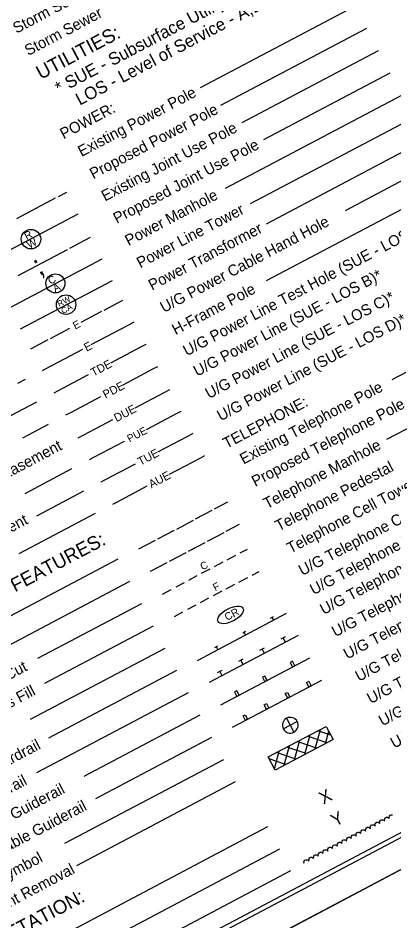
# Model space of a CAD drawing. Extents: x 1487118 to 1489121, y 496367 to 498126.
# Drawn here: x 1488120 to 1488418, y 496745 to 497462 of the extents above; entities that cross this region are included whole.
import ezdxf

# ---------------------------------------------------------------- set-up
doc = ezdxf.new("R2010")
doc.units = 0
for name, color, linetype in [('Prop Easement Permanent Drainage Utility', 7, 'Continuous'), ('Prop WCC CELL', 7, 'Continuous'), ('Sheet Cutting Line CELL', 7, 'Continuous'), ('Sheet Plot Border Inside CELL', 7, 'Continuous'), ('Sheet Plot Border Outside CELL', 7, 'Continuous'), ('Sheet Symbology CELL', 7, 'Continuous')]:
    doc.layers.add(name, color=color, linetype=linetype)

msp = doc.modelspace()

# ---------------------------------------------------------------- linework, layer by layer
at = {"layer": 'Prop Easement Permanent Drainage Utility'}
for p, q in [((1488212.57, 497152.15), (1488240.16, 497166.72)), ((1488167.2, 497128.2), (1488194.88, 497142.81))]:
    msp.add_line(p, q, dxfattribs=at)
at = {"layer": 'Prop WCC CELL'}
msp.add_ellipse((1488288.33, 496987.68), major_axis=(9.92, 5.24), ratio=0.462467, dxfattribs=at)
at = {"layer": 'Sheet Cutting Line CELL'}
msp.add_line((1487631.63, 496367.31), (1489120.78, 497153.62), dxfattribs=at)
at = {"layer": 'Sheet Plot Border Inside CELL'}
msp.add_lwpolyline([(1487632.64, 496393.24), (1489106.32, 497171.37), (1488613.66, 498104.39), (1487139.99, 497326.26)], close=True, dxfattribs=at)
at = {"layer": 'Sheet Plot Border Outside CELL'}
msp.add_lwpolyline([(1487631.63, 496367.31), (1489120.78, 497153.62), (1488607.16, 498126.35), (1487118.01, 497340.04)], close=True, dxfattribs=at)
at = {"layer": 'Sheet Symbology CELL'}
for p, q in [((1488386.91, 497470.85), (1488264.26, 497406.09)), ((1488396.25, 497453.16), (1488280.49, 497392.04)), ((1488405.59, 497435.48), (1488297.25, 497378.27)), ((1488414.93, 497417.79), (1488314.55, 497364.79)), ((1488424.27, 497400.11), (1488284.11, 497326.1)), ((1488433.61, 497382.42), (1488304.06, 497314.02)), ((1488442.95, 497364.73), (1488316.58, 497298.01)), ((1488452.28, 497347.05), (1488379.48, 497308.61)), ((1488151.63, 497319.88), (1488158.27, 497323.38)), ((1488461.62, 497329.36), (1488316.69, 497252.83)), ((1488118.47, 497302.37), (1488149.42, 497318.71)), ((1488094.44, 497267.57), (1488167.39, 497306.1)), ((1488160.73, 497278.83), (1488177.2, 497287.53)), ((1488119.69, 497257.16), (1488158.96, 497277.9)), ((1488113.32, 497231.82), (1488186.28, 497270.34)), ((1488121.51, 497214.76), (1488194.46, 497253.28)), ((1488187.99, 497229.68), (1488202.79, 497237.49)), ((1488169.64, 497219.99), (1488186.22, 497228.74)), ((1488515.56, 497226.63), (1488416.62, 497174.39)), ((1488177.7, 497202.25), (1488207.55, 497218.01)), ((1488207.55, 497218.01), (1488211.87, 497220.29)), ((1488145.32, 497207.15), (1488160.79, 497215.32)), ((1488129.83, 497198.97), (1488143.55, 497206.21)), ((1488217.54, 497200.67), (1488221.21, 497202.6)), ((1488141.23, 497182.99), (1488171.07, 497198.75)), ((1488193.22, 497187.83), (1488217.54, 497200.67)), ((1488534.24, 497191.26), (1488412.32, 497126.89)), ((1488138.92, 497181.77), (1488141.23, 497182.99)), ((1488202.96, 497170.35), (1488227.28, 497183.19)), ((1488227.28, 497183.19), (1488230.55, 497184.92)), ((1488125.08, 497174.46), (1488119.18, 497171.35)), ((1488151.22, 497165.65), (1488175.54, 497178.49)), ((1488148.25, 497164.08), (1488151.22, 497165.65)), ((1488160.95, 497148.17), (1488185.27, 497161.01)), ((1488134.08, 497156.6), (1488113.61, 497145.79)), ((1488157.59, 497146.4), (1488160.95, 497148.17)), ((1488221.67, 497134.99), (1488245.99, 497147.83)), ((1488245.99, 497147.83), (1488249.23, 497149.54)), ((1488143.42, 497138.91), (1488122.95, 497128.1)), ((1488230.58, 497117.07), (1488254.9, 497129.91)), ((1488254.9, 497129.91), (1488258.57, 497131.85)), ((1488179.67, 497112.81), (1488203.99, 497125.65)), ((1488176.27, 497111.02), (1488179.67, 497112.81)), ((1488239.92, 497099.39), (1488264.24, 497112.23)), ((1488264.24, 497112.23), (1488267.91, 497114.17)), ((1488162.1, 497103.53), (1488124.84, 497083.86)), ((1488188.58, 497094.89), (1488212.89, 497107.74)), ((1488185.61, 497093.33), (1488188.58, 497094.89)), ((1488197.91, 497077.21), (1488222.23, 497090.05)), ((1488171.44, 497085.85), (1488134.18, 497066.17)), ((1488194.95, 497075.64), (1488197.91, 497077.21)), ((1488275.64, 497071.77), (1488286.25, 497077.37)), ((1488180.78, 497068.16), (1488120.24, 497036.2)), ((1488260.6, 497063.83), (1488273.87, 497070.83)), ((1488245.57, 497055.89), (1488258.83, 497062.9)), ((1488284.97, 497054.08), (1488295.59, 497059.69)), ((1488230.54, 497047.96), (1488243.8, 497054.96)), ((1488269.94, 497046.14), (1488283.21, 497053.15)), ((1488215.5, 497040.02), (1488228.77, 497047.02)), ((1488254.91, 497038.21), (1488268.17, 497045.21)), ((1488239.87, 497030.27), (1488253.14, 497037.27)), ((1488301.48, 497039.64), (1488295.82, 497036.65)), ((1488198.85, 497031.87), (1488108.34, 496984.08)), ((1488292.37, 497034.83), (1488285.43, 497031.17)), ((1488224.84, 497022.33), (1488238.11, 497029.34)), ((1488272.03, 497024.09), (1488265.13, 497020.45)), ((1488282.15, 497029.44), (1488275.3, 497025.82)), ((1488261.64, 497018.61), (1488254.92, 497015.06)), ((1488301.71, 497017.15), (1488294.76, 497013.48)), ((1488310.81, 497021.96), (1488305.15, 497018.97)), ((1488208.19, 497014.19), (1488060.38, 496936.14)), ((1488251.47, 497013.24), (1488244.79, 497009.71)), ((1488291.49, 497011.75), (1488284.64, 497008.13)), ((1488234.4, 497004.23), (1488241.12, 497007.77)), ((1488270.98, 497000.92), (1488264.26, 496997.37)), ((1488281.37, 497006.41), (1488274.47, 497002.77)), ((1488217.53, 496996.5), (1488135.12, 496952.99)), ((1488260.81, 496995.55), (1488254.13, 496992.03)), ((1488243.74, 496986.54), (1488250.46, 496990.09)), ((1488262, 496951.62), (1488332.75, 496988.97)), ((1488320.2, 496985.18), (1488322.41, 496986.35)), ((1488322.48, 496983.55), (1488321.31, 496985.76)), ((1488226.86, 496978.82), (1488140.44, 496933.18)), ((1488298.1, 496973.51), (1488300.31, 496974.67)), ((1488300.37, 496971.88), (1488299.2, 496974.09)), ((1488342.08, 496971.29), (1488271.34, 496933.93)), ((1488328.5, 496968.58), (1488332.04, 496970.45)), ((1488332.11, 496966.02), (1488330.27, 496969.52)), ((1488236.2, 496961.13), (1488129.27, 496904.67)), ((1488275.99, 496961.83), (1488278.2, 496963)), ((1488278.26, 496960.21), (1488277.09, 496962.42)), ((1488311.7, 496959.71), (1488315.24, 496961.58)), ((1488315.31, 496957.15), (1488313.47, 496960.65)), ((1488280.68, 496916.25), (1488351.42, 496953.6)), ((1488294.9, 496950.84), (1488298.43, 496952.71)), ((1488298.51, 496948.28), (1488296.67, 496951.77)), ((1488245.35, 496943.48), (1488143.8, 496889.86)), ((1488278.1, 496941.97), (1488281.63, 496943.84)), ((1488281.71, 496939.41), (1488279.86, 496942.9)), ((1488290.02, 496898.56), (1488360.76, 496935.92)), ((1488254.69, 496925.79), (1488134.21, 496862.18)), ((1488264.02, 496908.11), (1488171.79, 496859.4)), ((1488332.9, 496905.64), (1488335.82, 496900.12)), ((1488335.82, 496900.12), (1488341.34, 496903.03)), ((1488318.29, 496874.89), (1488364.36, 496899.22)), ((1488330.29, 496897.2), (1488335.82, 496900.12)), ((1488335.82, 496900.12), (1488338.73, 496894.59)), ((1488355.59, 496881.35), (1488359.81, 496896.81)), ((1488368.08, 496892.19), (1488357.78, 496895.74)), ((1488363.77, 496885.67), (1488366.42, 496895.33)), ((1488364.36, 496899.22), (1488369.83, 496888.87)), ((1488273.36, 496890.42), (1488181.13, 496841.72)), ((1488369.83, 496888.87), (1488323.76, 496864.54)), ((1488339.14, 496872.67), (1488343.45, 496888.17)), ((1488356.56, 496881.87), (1488341.37, 496887.08)), ((1488347.37, 496877.01), (1488351.63, 496892.49)), ((1488364.79, 496886.21), (1488349.55, 496891.39)), ((1488323.22, 496865.56), (1488327, 496879.49)), ((1488330.96, 496868.35), (1488335.23, 496883.83)), ((1488348.34, 496877.52), (1488333.19, 496882.76)), ((1488282.7, 496872.73), (1488156.58, 496806.14)), ((1488323.76, 496864.54), (1488318.29, 496874.89)), ((1488318.57, 496874.36), (1488318.78, 496875.15)), ((1488331.94, 496868.86), (1488319.13, 496873.3)), ((1488340.16, 496873.2), (1488324.97, 496878.41)), ((1488292.04, 496855.05), (1488165.92, 496788.45)), ((1488415.09, 496828.59), (1488415.93, 496829.03)), ((1488415.93, 496829.03), (1488416.87, 496828.97)), ((1488416.87, 496828.97), (1488416.94, 496828.94)), ((1488403.09, 496821.01), (1488403.32, 496821.87)), ((1488403.32, 496821.87), (1488403.82, 496822.64)), ((1488403.82, 496822.64), (1488404.66, 496823.08)), ((1488404.66, 496823.08), (1488405.6, 496823.01)), ((1488405.6, 496823.01), (1488406.39, 496822.69)), ((1488406.39, 496822.69), (1488406.96, 496822.04)), ((1488406.85, 496823), (1488407.08, 496823.85)), ((1488407.03, 496822.02), (1488406.85, 496823)), ((1488407.08, 496823.85), (1488407.58, 496824.62)), ((1488407.58, 496824.62), (1488408.42, 496825.07)), ((1488408.42, 496825.07), (1488409.36, 496825)), ((1488409.36, 496825), (1488410.15, 496824.68)), ((1488410.15, 496824.68), (1488410.72, 496824.02)), ((1488410.61, 496824.98), (1488410.84, 496825.83)), ((1488410.79, 496824), (1488410.61, 496824.98)), ((1488410.84, 496825.83), (1488411.33, 496826.61)), ((1488411.33, 496826.61), (1488412.18, 496827.05)), ((1488412.18, 496827.05), (1488413.12, 496826.98)), ((1488413.12, 496826.98), (1488413.91, 496826.66)), ((1488413.91, 496826.66), (1488414.48, 496826)), ((1488414.37, 496826.96), (1488414.6, 496827.82)), ((1488414.55, 496825.98), (1488414.37, 496826.96)), ((1488414.6, 496827.82), (1488415.09, 496828.59)), ((1488317.85, 496819.32), (1488157.68, 496734.75)), ((1488388.29, 496813.93), (1488388.79, 496814.7)), ((1488388.79, 496814.7), (1488389.63, 496815.14)), ((1488389.63, 496815.14), (1488390.57, 496815.07)), ((1488390.57, 496815.07), (1488391.36, 496814.76)), ((1488391.36, 496814.76), (1488391.93, 496814.1)), ((1488391.82, 496815.06), (1488392.05, 496815.91)), ((1488392, 496814.08), (1488391.82, 496815.06)), ((1488392.05, 496815.91), (1488392.54, 496816.68)), ((1488392.54, 496816.68), (1488393.38, 496817.13)), ((1488393.38, 496817.13), (1488394.32, 496817.06)), ((1488394.32, 496817.06), (1488395.11, 496816.74)), ((1488395.11, 496816.74), (1488395.69, 496816.08)), ((1488395.58, 496817.04), (1488395.8, 496817.9)), ((1488395.76, 496816.06), (1488395.58, 496817.04)), ((1488395.8, 496817.9), (1488396.3, 496818.67)), ((1488396.3, 496818.67), (1488397.14, 496819.11)), ((1488397.14, 496819.11), (1488398.08, 496819.04)), ((1488398.08, 496819.04), (1488398.87, 496818.73)), ((1488398.87, 496818.73), (1488399.45, 496818.07)), ((1488399.34, 496819.03), (1488399.56, 496819.88)), ((1488399.51, 496818.05), (1488399.34, 496819.03)), ((1488399.56, 496819.88), (1488400.06, 496820.65)), ((1488400.06, 496820.65), (1488400.9, 496821.1)), ((1488400.9, 496821.1), (1488401.84, 496821.03)), ((1488401.84, 496821.03), (1488402.63, 496820.71)), ((1488402.63, 496820.71), (1488403.2, 496820.05)), ((1488403.27, 496820.03), (1488403.09, 496821.01)), ((1488376.79, 496807.12), (1488377.01, 496807.97)), ((1488377.01, 496807.97), (1488377.51, 496808.75)), ((1488377.51, 496808.75), (1488378.35, 496809.19)), ((1488378.35, 496809.19), (1488379.29, 496809.12)), ((1488379.29, 496809.12), (1488380.08, 496808.8)), ((1488380.08, 496808.8), (1488380.66, 496808.14)), ((1488380.54, 496809.1), (1488380.77, 496809.96)), ((1488380.72, 496808.12), (1488380.54, 496809.1)), ((1488380.77, 496809.96), (1488381.27, 496810.73)), ((1488381.27, 496810.73), (1488382.11, 496811.17)), ((1488382.11, 496811.17), (1488383.05, 496811.11)), ((1488383.05, 496811.11), (1488383.84, 496810.79)), ((1488383.84, 496810.79), (1488384.41, 496810.13)), ((1488384.3, 496811.09), (1488384.53, 496811.94)), ((1488384.48, 496810.11), (1488384.3, 496811.09)), ((1488384.53, 496811.94), (1488385.03, 496812.72)), ((1488385.03, 496812.72), (1488385.87, 496813.16)), ((1488385.87, 496813.16), (1488386.81, 496813.09)), ((1488386.81, 496813.09), (1488387.6, 496812.77)), ((1488387.6, 496812.77), (1488388.17, 496812.11)), ((1488388.06, 496813.07), (1488388.29, 496813.93)), ((1488388.24, 496812.09), (1488388.06, 496813.07)), ((1488327.18, 496801.63), (1488167.02, 496717.06)), ((1488361.98, 496800.04), (1488362.48, 496800.81)), ((1488362.48, 496800.81), (1488363.32, 496801.25)), ((1488363.32, 496801.25), (1488364.26, 496801.18)), ((1488364.26, 496801.18), (1488365.05, 496800.87)), ((1488365.05, 496800.87), (1488365.62, 496800.21)), ((1488365.51, 496801.17), (1488365.74, 496802.02)), ((1488365.69, 496800.19), (1488365.51, 496801.17)), ((1488365.74, 496802.02), (1488366.24, 496802.79)), ((1488366.24, 496802.79), (1488367.08, 496803.24)), ((1488367.08, 496803.24), (1488368.02, 496803.17)), ((1488368.02, 496803.17), (1488368.81, 496802.85)), ((1488368.81, 496802.85), (1488369.38, 496802.19)), ((1488369.27, 496803.15), (1488369.5, 496804.01)), ((1488369.45, 496802.17), (1488369.27, 496803.15)), ((1488369.5, 496804.01), (1488369.99, 496804.78)), ((1488369.99, 496804.78), (1488370.83, 496805.22)), ((1488370.83, 496805.22), (1488371.78, 496805.15)), ((1488371.78, 496805.15), (1488372.57, 496804.83)), ((1488372.57, 496804.83), (1488373.14, 496804.18)), ((1488373.03, 496805.14), (1488373.26, 496805.99)), ((1488373.21, 496804.16), (1488373.03, 496805.14)), ((1488373.26, 496805.99), (1488373.75, 496806.76)), ((1488373.75, 496806.76), (1488374.59, 496807.21)), ((1488374.59, 496807.21), (1488375.53, 496807.14)), ((1488375.53, 496807.14), (1488376.32, 496806.82)), ((1488376.32, 496806.82), (1488376.9, 496806.16)), ((1488376.96, 496806.14), (1488376.79, 496807.12)), ((1488347.44, 496792.87), (1488348.28, 496793.31)), ((1488348.28, 496793.31), (1488349.23, 496793.25)), ((1488349.23, 496793.25), (1488350.02, 496792.93)), ((1488350.02, 496792.93), (1488350.59, 496792.27)), ((1488350.48, 496793.23), (1488350.71, 496794.08)), ((1488350.66, 496792.25), (1488350.48, 496793.23)), ((1488350.71, 496794.08), (1488351.2, 496794.86)), ((1488351.2, 496794.86), (1488352.04, 496795.3)), ((1488352.04, 496795.3), (1488352.98, 496795.23)), ((1488352.98, 496795.23), (1488353.77, 496794.91)), ((1488353.77, 496794.91), (1488354.35, 496794.25)), ((1488354.24, 496795.21), (1488354.46, 496796.07)), ((1488354.42, 496794.23), (1488354.24, 496795.21)), ((1488354.46, 496796.07), (1488354.96, 496796.84)), ((1488354.96, 496796.84), (1488355.8, 496797.28)), ((1488355.8, 496797.28), (1488356.74, 496797.21)), ((1488356.74, 496797.21), (1488357.53, 496796.9)), ((1488357.53, 496796.9), (1488358.11, 496796.24)), ((1488358, 496797.2), (1488358.22, 496798.05)), ((1488358.17, 496796.22), (1488358, 496797.2)), ((1488358.22, 496798.05), (1488358.72, 496798.82)), ((1488358.72, 496798.82), (1488359.56, 496799.27)), ((1488359.56, 496799.27), (1488360.5, 496799.2)), ((1488360.5, 496799.2), (1488361.29, 496798.88)), ((1488361.29, 496798.88), (1488361.86, 496798.22)), ((1488361.75, 496799.18), (1488361.98, 496800.04)), ((1488361.93, 496798.2), (1488361.75, 496799.18)), ((1488346.72, 496791.24), (1488346.95, 496792.1)), ((1488346.9, 496790.26), (1488346.72, 496791.24)), ((1488346.95, 496792.1), (1488347.44, 496792.87)), ((1488335.94, 496784.48), (1488147.86, 496685.17))]:
    msp.add_line(p, q, dxfattribs=at)
for points in [[(1488603.8, 498096.3), (1487277.36, 497395.91), (1487767.16, 496468.3), (1489093.6, 497168.69)], [(1488337.69, 496946.35), (1488339.46, 496947.29), (1488337.59, 496950.83), (1488335.83, 496949.89)], [(1488315.59, 496934.68), (1488317.35, 496935.61), (1488315.49, 496939.15), (1488313.72, 496938.22)], [(1488348.69, 496934.07), (1488350.46, 496935), (1488352.33, 496931.46), (1488350.56, 496930.53)], [(1488293.48, 496923.01), (1488295.25, 496923.94), (1488293.38, 496927.48), (1488291.61, 496926.54)], [(1488331.89, 496925.2), (1488333.66, 496926.13), (1488335.53, 496922.59), (1488333.76, 496921.66)], [(1488315.09, 496916.32), (1488316.86, 496917.26), (1488318.72, 496913.72), (1488316.96, 496912.79)], [(1488298.29, 496907.45), (1488300.05, 496908.39), (1488301.92, 496904.85), (1488300.15, 496903.92)]]:
    msp.add_lwpolyline(points, close=True, dxfattribs=at)
for centre, radius in [((1488129.78, 497286), 7.75), ((1488149.22, 497250.89), 7.58), ((1488157.68, 497234.03), 7.72)]:
    msp.add_circle(centre, radius, dxfattribs=at)
for start, end in [(117.82948, 207.83402), (27.82948, 117.83402), (297.82948, 27.83402), (207.82948, 297.83402)]:
    msp.add_arc((1488335.82, 496900.11), 6.25, start, end, dxfattribs=at)

# ---------------------------------------------------------------- texts
at = {"layer": 'Prop Easement Permanent Drainage Utility'}
msp.add_text('DUE', height=6.55, rotation=27.83509, dxfattribs=at).set_placement((1488197.83, 497140.64))
at = {"layer": 'Prop WCC CELL'}
msp.add_text('CR', height=6, rotation=27.83509, dxfattribs=at).set_placement((1488285.54, 496982.86))
at = {"layer": 'Sheet Symbology CELL'}
for s, height, p in [('LOS - Level of Service - A,B,C or D (Accuracy) ', 9.9, (1488168.55, 497391.93)), ('* SUE - Subsurface Utility Engineering', 9.9, (1488152.2, 497400.91)), ('Storm Sewer Manhole', 8.75, (1488118.29, 497449.03)), ('Storm Sewer', 8.75, (1488127.62, 497431.34)), ('UTILITIES:', 11, (1488137.59, 497412.44)), ('Existing Power Pole', 8.75, (1488169.96, 497351.16)), ('POWER:', 8.75, (1488155.75, 497365.14)), ('Proposed Power Pole', 8.75, (1488179.3, 497333.48)), ('Existing Joint Use Pole', 8.75, (1488188.63, 497315.8)), ('Proposed Joint Use Pole', 8.75, (1488197.99, 497298.11)), ('Power Manhole', 8.75, (1488207.32, 497280.42)), ('Power Line Tower', 8.75, (1488216.66, 497262.75)), ('U/G Power Cable Hand Hole', 8.75, (1488235.35, 497227.37)), ('U/G Power Line Test Hole (SUE - LOS A)*', 8.75, (1488253.55, 497192.91)), ('Power Transformer', 8.75, (1488225.99, 497245.06)), ('R', 6.07, (1488126.4, 497285.25)), ('W', 6.07, (1488128.52, 497278.28)), (';', 16.5, (1488136.18, 497256.61)), ('U/G Power Line (SUE - LOS B)*', 8.75, (1488261.79, 497176.71)), ('C', 5.94, (1488145.24, 497249.8)), ('A', 5.94, (1488149.09, 497243.76)), ('H-Frame Pole', 8.75, (1488244.69, 497209.69)), ('RW', 4.838, (1488152.31, 497232.06)), ('U/G Power Line (SUE - LOS C)*', 8.75, (1488271.16, 497159.03)), ('CA', 4.838, (1488155.31, 497226.53)), ('U/G Power Line (SUE - LOS D)*', 8.75, (1488280.52, 497141.34)), ('E', 6, (1488165.02, 497214.16)), ('E', 6.55, (1488174.03, 497196.58)), ('TDE', 6.55, (1488179.38, 497176.78)), ('PDE', 6.55, (1488189.02, 497159.26)), ('Existing Telephone Pole', 8.75, (1488298.63, 497106.95)), ('TELEPHONE:', 8.75, (1488285.19, 497119.41)), ('Proposed Telephone Pole', 8.75, (1488307.96, 497089.27)), ('PUE', 6, (1488208.13, 497124.44)), ('Proposed Permanent Drainage/Utility Easement', 8.75, (1487935, 497003.03)), ('Telephone Manhole', 8.75, (1488317.3, 497071.58)), ('TUE', 6.55, (1488216.72, 497106.02)), ('Telephone Pedestal', 8.75, (1488326.64, 497053.9)), ('U/G Telephone Test Hole (SUE - LOS A)*', 8.75, (1488354.31, 497003.28)), ('AUE', 6.55, (1488225.48, 497088.03)), ('U/G Telephone Cable Hand Hole', 8.75, (1488345.33, 497018.53)), ('Telephone Cell Tower', 8.75, (1488335.99, 497036.22)), ('U/G Telephone Cable (SUE - LOS B)*', 8.75, (1488362.29, 496987.57)), ('Proposed Temporary Utility Easement', 8.75, (1487953.41, 496968.16)), ('U/G Telephone Cable (SUE - LOS C)*', 8.75, (1488371.63, 496969.89)), ('U/G Telephone Cable (SUE - LOS D)*', 8.75, (1488380.97, 496952.2)), ('ROADS AND RELATED FEATURES:', 11, (1487972.57, 496929.18)), ('U/G Telephone Conduit (SUE - LOS B)*', 8.75, (1488390.31, 496934.51)), ('C', 5.93, (1488266.13, 497022.94)), ('U/G Telephone Conduit (SUE - LOS C)*', 8.75, (1488399.65, 496916.83)), ('F', 5.93, (1488276.24, 497006.37)), ('U/G Telephone Conduit (SUE - LOS D)*', 8.75, (1488408.99, 496899.14)), ('U/G Fiber Optics Cable (SUE - LOS B)*', 8.75, (1488418.33, 496881.46)), ('Proposed Slope Stakes Cut', 8.75, (1488000.57, 496876.8)), ('Proposed Slope Stakes Fill', 8.75, (1488009.9, 496859.11)), ('Existing Metal Guardrail', 8.75, (1488028.39, 496823.77)), ('Proposed Guardrail', 8.75, (1488037.73, 496806.1)), ('Existing Cable Guiderail', 8.75, (1488047.07, 496788.42)), ('X', 10, (1488362.09, 496837.03)), ('Proposed Cable Guiderail', 8.75, (1488056.41, 496770.73)), ('Y', 10, (1488371.43, 496819.34)), ('Equality Symbol', 8.75, (1488065.75, 496753.05)), ('Pavement Removal', 8.75, (1488075.09, 496735.36)), ('VEGETATION:', 11, (1488086.12, 496714.43))]:
    msp.add_text(s, height=height, rotation=27.83509, dxfattribs=at).set_placement(p)

doc.saveas('drawing.dxf')
